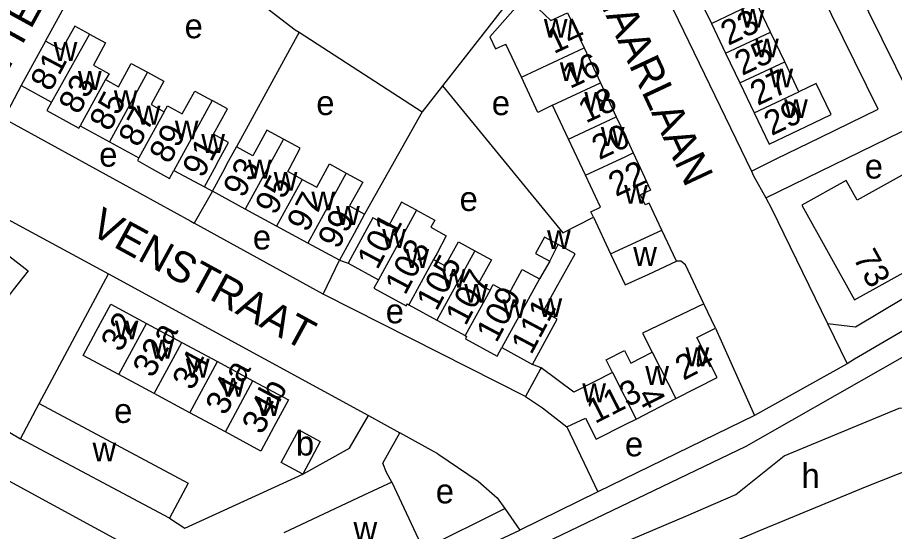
# Model space of a CAD drawing. Extents: x 158356 to 159894, y 383831 to 385260.
# Drawn here: x 159000.7 to 159143.9, y 383940.7 to 384024.6 of the extents above; entities that cross this region are included whole.
import ezdxf

# ---------------------------------------------------------------- set-up
doc = ezdxf.new("R2010")
doc.units = 0
for name, color, linetype in [('BLT_Basislijn', 7, 'Continuous'), ('BLT_Bebouwing', 7, 'Continuous'), ('BLT_Centroide', 7, 'Continuous'), ('BLT_Huisnummer', 7, 'Continuous'), ('BLT_Huisnummer_ tussenligend', 7, 'Continuous'), ('BLT_Huisnummer_reeks', 7, 'Continuous'), ('BLT_Onderverdeling_panden', 7, 'Continuous'), ('BLT_Straatnaam', 7, 'Continuous'), ('BLT_Vlakafsluiter', 7, 'Continuous')]:
    doc.layers.add(name, color=color, linetype=linetype)

msp = doc.modelspace()

# ---------------------------------------------------------------- linework, layer by layer
at = {"layer": 'BLT_Basislijn'}
for p, q in [((159005.27, 384020.8), (159012.56, 384034.13)), ((159080.04, 384026.23), (159070.07, 384013.46)), ((159046.67, 384022.22), (159036.45, 384003.53)), ((159046.67, 384022.22), (159066.78, 384009.26)), ((159122.87, 383995.19), (159165.67, 384016.08)), ((159070.07, 384013.46), (159066.78, 384009.26)), ((159066.78, 384009.26), (159057.34, 383992.51)), ((159124.58, 384001.54), (159124.64, 384001.55)), ((159032.51, 383996.29), (159029.52, 383991.08)), ((159050.62, 383979.47), (159029.52, 383991.08)), ((159050.62, 383979.47), (159053.25, 383985)), ((159053.25, 383985), (159054.67, 383984.53)), ((159015.54, 383982.8), (159058, 383959.64)), ((159132.98, 383974.65), (159136.17, 383968.1)), ((159114.69, 383973.88), (159121.02, 383959.64)), ((159086.19, 383967.45), (159084.77, 383967.99)), ((159058, 383959.64), (159063.12, 383956.82)), ((158997.04, 383958.25), (159001.16, 383955.84)), ((159090.38, 383957.81), (159095.47, 383947.17)), ((158999.29, 383949), (159026.07, 383934.41)), ((159025.49, 383942.85), (159028.01, 383941.24)), ((159045.95, 383923.82), (159082.7, 383940.91))]:
    msp.add_line(p, q, dxfattribs=at)
for points in [[(159130.07, 384059.7), (159124.27, 384056.8), (159146.23, 384012.21), (159163.28, 384020.54)], [(159131.86, 384005.09), (159141.23, 384009.67), (159118.45, 384056), (159109.62, 384051.58)], [(159054.11, 384048.78), (159044.27, 384037.62), (159041.24, 384026.76), (159041.56, 384026.03), (159046.04, 384022.62), (159046.67, 384022.22)], [(159102.32, 384048.1), (159098.34, 384046.21), (159098.18, 384045.79), (159100, 384041.97), (159120.53, 383999.56)], [(159001.28, 384013.52), (158998.47, 384008.16), (159028.98, 383991.37), (159029.52, 383991.08)], [(159070.07, 384013.46), (159089.76, 383989.46), (159094.72, 383992.05)], [(159120.53, 383999.56), (159124.58, 384001.54), (159131.86, 384005.09)], [(159120.53, 383999.56), (159120.9, 383998.78), (159122.87, 383995.19)], [(159132.98, 383974.65), (159137.54, 383974.11), (159175.88, 383997.05)], [(159122.87, 383995.19), (159123.83, 383993.43), (159132.98, 383974.65)], [(158964.85, 383970.22), (158990.55, 383992.57), (158992.72, 383993.66), (158996.3, 383993.18), (159015.54, 383982.8)], [(159178.17, 383992.69), (159137.39, 383968.84), (159136.17, 383968.1)], [(159183.57, 383991.39), (159156.91, 383975.82), (159119.63, 383954.56), (159067.69, 383929.66)], [(159112.79, 383977.86), (159109.76, 383984.24), (159108.99, 383984.83), (159108.28, 383984.85)], [(159004.24, 383961.61), (159015.54, 383982.8)], [(159083.67, 383962.76), (159050.83, 383979.35), (159050.62, 383979.47)], [(159088.93, 383926.66), (159102.6, 383932.65), (159121.62, 383940.74), (159139.46, 383948.12), (159156.35, 383954.78), (159168.72, 383959.06), (159184.17, 383964.54), (159200.11, 383969.53), (159206.72, 383971.51)], [(159081.85, 383931.35), (159109.84, 383943.2), (159117.99, 383946.75), (159125.88, 383953.07), (159144.67, 383960.83), (159152.29, 383961.04)], [(159047.27, 383950.08), (159054.9, 383954.29), (159058, 383959.64)], [(159121.02, 383959.64), (159095.47, 383947.17)], [(159061.79, 383948.76), (159060.92, 383950.34), (159060.34, 383951.85), (159063.12, 383956.82)], [(159069.32, 383953.39), (159063.12, 383956.82)], [(159069.32, 383953.39), (159075.91, 383948.92), (159079.03, 383946.2), (159080.25, 383944.43)], [(159028.01, 383941.24), (159047.27, 383950.08)], [(159066.93, 383937.81), (159080.25, 383944.43)], [(159080.25, 383944.43), (159082.7, 383940.91)]]:
    msp.add_lwpolyline(points, dxfattribs=at)
at = {"layer": 'BLT_Bebouwing'}
for p, q in [((159111.66, 384028.56), (159113.99, 384023.68)), ((159123.64, 384022.27), (159121.31, 384027.13)), ((159087.76, 384024.14), (159090.52, 384025.43)), ((159090.52, 384025.43), (159093.2, 384019.7)), ((159113.99, 384023.68), (159116.32, 384018.83)), ((159125.97, 384017.4), (159123.64, 384022.27)), ((159005.27, 384020.8), (159001.28, 384013.52)), ((159082.97, 384014.91), (159080.44, 384020.31)), ((159093.2, 384019.7), (159095.87, 384013.98)), ((159116.32, 384018.83), (159118.65, 384013.96)), ((159128.3, 384012.52), (159125.97, 384017.4)), ((159001.28, 384013.52), (159006.22, 384010.81)), ((159095.87, 384013.98), (159098.47, 384008.43)), ((159118.65, 384013.96), (159120.99, 384009.06)), ((159090.66, 384004.76), (159088.05, 384010.31)), ((159120.99, 384009.06), (159123.44, 384003.94)), ((159010.91, 384006.94), (159015.7, 384004.32)), ((159093.43, 383998.87), (159090.66, 384004.76)), ((159131.89, 384005.02), (159131.86, 384005.09)), ((159015.7, 384004.32), (159020.48, 384001.7)), ((159124.58, 384001.54), (159124.59, 384001.53)), ((159124.59, 384001.53), (159124.64, 384001.55)), ((159026.23, 383999.65), (159031.23, 383996.98)), ((159095.87, 383993.65), (159093.43, 383998.87)), ((159031.23, 383996.98), (159032.51, 383996.29)), ((159037.87, 383993.36), (159032.51, 383996.29)), ((159043, 383990.57), (159037.87, 383993.36)), ((159094.72, 383992.05), (159097.55, 383986.02)), ((159048.09, 383987.8), (159043, 383990.57)), ((159108.28, 383984.85), (159105.91, 383989.92)), ((159053.25, 383985), (159048.09, 383987.8)), ((159054.67, 383984.53), (159059.63, 383981.81)), ((159064.59, 383977.74), (159069.19, 383975.22)), ((159114.69, 383973.88), (159112.79, 383977.86)), ((159021.74, 383974.69), (159027.54, 383971.57)), ((159069.19, 383975.22), (159073.81, 383972.69)), ((159111.6, 383972.4), (159114.69, 383973.88)), ((159027.54, 383971.57), (159033.34, 383968.44)), ((159079.78, 383970.73), (159084.77, 383967.99)), ((159033.34, 383968.44), (159039.14, 383965.31)), ((159023.03, 383963.21), (159017.23, 383966.33)), ((159028.83, 383960.08), (159023.03, 383963.21)), ((159001.16, 383955.84), (159004.24, 383961.61)), ((159101.71, 383959.07), (159108.2, 383962.43)), ((159034.63, 383956.95), (159028.83, 383960.08)), ((159025.49, 383942.85), (159001.16, 383955.84)), ((159061.79, 383948.76), (159066.93, 383937.81))]:
    msp.add_line(p, q, dxfattribs=at)
for points in [[(159087.76, 384024.14), (159083.63, 384028.13), (159077.84, 384021.48), (159078.75, 384019.53), (159080.44, 384020.31)], [(159012.46, 384021.91), (159010.03, 384023.22), (159007.9, 384019.36), (159005.27, 384020.8)], [(159012.46, 384021.91), (159015.05, 384020.49), (159013.11, 384016.83), (159015.65, 384015.44), (159015.06, 384014.51)], [(159015.06, 384014.51), (159017.18, 384013.34), (159019.27, 384017.15), (159021.93, 384015.69)], [(159021.93, 384015.69), (159024.59, 384014.23), (159022.5, 384010.41), (159024.62, 384009.25)], [(159088.05, 384010.31), (159085.66, 384009.15), (159082.97, 384014.91)], [(159130.74, 384007.42), (159133.57, 384008.79), (159131.12, 384013.88), (159128.3, 384012.52)], [(159024.62, 384009.25), (159025.16, 384010.24), (159027.6, 384008.91), (159029.64, 384012.63), (159032.48, 384011.07)], [(159006.22, 384010.81), (159005.46, 384009.43), (159010.7, 384006.55), (159010.91, 384006.94)], [(159031.23, 383996.98), (159032.87, 384000), (159033.59, 384001.33), (159035.17, 384004.23), (159032.71, 384005.58), (159034.98, 384009.7), (159032.48, 384011.07)], [(159137.34, 383978.53), (159171.42, 383997.44), (159164.61, 384009.71), (159137.81, 383994.83), (159136.03, 383998.02), (159128.76, 383993.98), (159137.34, 383978.53)], [(159098.47, 384008.43), (159100, 384005.15), (159101.22, 384002.53)], [(159123.44, 384003.94), (159130.74, 384007.42)], [(159044.13, 384004.78), (159041.43, 384006.26), (159039.13, 384002.07), (159036.45, 384003.53)], [(159047.18, 383998.21), (159044.82, 383999.51), (159045.08, 384000), (159046.84, 384003.3), (159044.13, 384004.78)], [(159032.51, 383996.29), (159034.53, 384000), (159034.9, 384000.68), (159036.45, 384003.53)], [(159020.48, 384001.7), (159020.26, 384001.3), (159022.56, 384000), (159025.49, 383998.35), (159026.23, 383999.65)], [(159101.22, 384002.53), (159102.4, 384000), (159104.08, 383996.43), (159102.43, 383995.66)], [(159047.18, 383998.21), (159049.56, 383996.92), (159051.64, 384000.72), (159054.35, 383999.24)], [(159054.35, 383999.24), (159057.06, 383997.76), (159054.93, 383993.87), (159057.34, 383992.51)], [(159065.84, 383993.16), (159063.42, 383994.49), (159061.26, 383990.54), (159058.72, 383991.93), (159057.07, 383988.92), (159054.67, 383984.53)], [(159105.91, 383989.92), (159103.84, 383994.34), (159103.2, 383994.03), (159102.43, 383995.66)], [(159065.84, 383993.16), (159068.82, 383991.53), (159068.2, 383990.4), (159070.71, 383989), (159069.2, 383986.15), (159068.64, 383985.12)], [(159094.72, 383992.05), (159094.31, 383992.92), (159095.87, 383993.65)], [(159057.34, 383992.51), (159055.65, 383989.38), (159053.25, 383985)], [(158990.93, 383983.92), (158994.94, 383989.05), (159000, 383985.15), (159002.42, 383983.26), (159000, 383980.16), (158999.34, 383979.32), (158998.39, 383978.09)], [(159089, 383987.55), (159086.75, 383988.77), (159085.3, 383986.1), (159087.64, 383984.83)], [(159068.64, 383985.12), (159070.54, 383984.08), (159072.68, 383988), (159075.38, 383986.52)], [(159084.77, 383967.99), (159087.18, 383972.38), (159088.81, 383975.37), (159086.52, 383976.63), (159088.63, 383980.49), (159091.74, 383986.07), (159089, 383987.55)], [(159075.38, 383986.52), (159078.07, 383985.05), (159075.94, 383981.15), (159077.87, 383980.09)], [(159097.55, 383986.02), (159099.92, 383980.98), (159103.76, 383982.73), (159108.28, 383984.85)], [(159087.64, 383984.83), (159085.93, 383981.96)], [(159077.87, 383980.09), (159078.37, 383981.01), (159080.96, 383979.59), (159083.11, 383983.51), (159085.93, 383981.96)], [(159059.63, 383981.81), (159058.88, 383980.44), (159064.18, 383977.54), (159064.36, 383977.86), (159064.59, 383977.74)], [(159017.23, 383966.33), (159011.43, 383969.46), (159013.56, 383973.42), (159015.94, 383977.82), (159021.74, 383974.69)], [(159112.79, 383977.86), (159102.77, 383973.07), (159104.34, 383970)], [(159073.81, 383972.69), (159074.03, 383972.57), (159073.82, 383972.18), (159079.02, 383969.34), (159079.78, 383970.73)], [(159108.2, 383962.43), (159114.93, 383965.86), (159111.6, 383972.4)], [(159097.83, 383966.68), (159096.79, 383968.72), (159099.79, 383970.24), (159100.82, 383968.2), (159104.34, 383970)], [(159086.19, 383967.45), (159086.04, 383967.17), (159083.67, 383962.76)], [(159097.83, 383966.68), (159091.51, 383963.46), (159086.19, 383967.45)], [(159039.14, 383965.31), (159044.93, 383962.18), (159042.56, 383957.78), (159040.43, 383953.83), (159034.63, 383956.95)], [(159004.24, 383961.61), (159028.56, 383948.59), (159025.49, 383942.85)], [(159083.67, 383962.76), (159086.42, 383960.9), (159090.38, 383957.81)], [(159090.38, 383957.81), (159093.43, 383959.22), (159095.19, 383955.8), (159100, 383958.25), (159101.71, 383959.07)], [(159061.79, 383948.76), (159057.26, 383946.64), (159044.2, 383940.5)]]:
    msp.add_lwpolyline(points, dxfattribs=at)
msp.add_lwpolyline([(159047.27, 383950.08), (159043.75, 383951.98), (159046.62, 383957.29), (159050.13, 383955.39)], close=True, dxfattribs=at)
at = {"layer": 'BLT_Onderverdeling_panden'}
for p, q in [((159012.46, 384021.91), (159006.22, 384010.81)), ((159082.97, 384014.91), (159093.2, 384019.7)), ((159015.06, 384014.51), (159010.91, 384006.94)), ((159021.93, 384015.69), (159015.7, 384004.32)), ((159088.05, 384010.31), (159095.87, 384013.98)), ((159032.48, 384011.07), (159026.23, 383999.65)), ((159024.62, 384009.25), (159020.48, 384001.7)), ((159090.66, 384004.76), (159098.47, 384008.43)), ((159044.13, 384004.78), (159037.87, 383993.36)), ((159054.35, 383999.24), (159048.09, 383987.8)), ((159047.18, 383998.21), (159043, 383990.57)), ((159065.84, 383993.16), (159059.63, 383981.81)), ((159097.55, 383986.02), (159105.91, 383989.92)), ((159087.64, 383984.83), (159089, 383987.55)), ((159075.38, 383986.52), (159069.19, 383975.22)), ((159068.64, 383985.12), (159064.59, 383977.74)), ((159085.93, 383981.96), (159079.78, 383970.73)), ((159077.87, 383980.09), (159073.81, 383972.69)), ((159017.23, 383966.33), (159021.74, 383974.69)), ((159023.03, 383963.21), (159027.54, 383971.57)), ((159104.34, 383970), (159108.2, 383962.43)), ((159028.83, 383960.08), (159033.34, 383968.44)), ((159034.63, 383956.95), (159039.14, 383965.31))]:
    msp.add_line(p, q, dxfattribs=at)
for points in [[(159113.99, 384023.68), (159121.31, 384027.13)], [(159116.32, 384018.83), (159123.64, 384022.27)], [(159118.65, 384013.96), (159125.97, 384017.4)], [(159120.99, 384009.06), (159128.3, 384012.52)], [(159093.43, 383998.87), (159100, 384001.96), (159101.22, 384002.53)], [(159097.83, 383966.68), (159101.71, 383959.07)]]:
    msp.add_lwpolyline(points, dxfattribs=at)
at = {"layer": 'BLT_Vlakafsluiter'}
for p, q in [((159136.17, 383968.1), (159121.02, 383959.64)), ((159095.47, 383947.17), (159082.7, 383940.91))]:
    msp.add_line(p, q, dxfattribs=at)

# ---------------------------------------------------------------- texts
at = {"layer": 'BLT_Centroide'}
for s, p in [('w', (159118.81, 384022.97)), ('w', (159086.64, 384021.34)), ('e', (159027.98, 384021.25)), ('w', (159006.59, 384017.55)), ('w', (159121.14, 384018.12)), ('w', (159089.25, 384014.25)), ('w', (159010.56, 384012.81)), ('w', (159123.48, 384013.22)), ('w', (159016.42, 384009.69)), ('e', (159049.48, 384008.71)), ('e', (159078.14, 384008.69)), ('w', (159093.26, 384009.38)), ('w', (159020.16, 384007.16)), ('w', (159125.88, 384008.22)), ('w', (159026.38, 384004.73)), ('w', (159095.95, 384003.66)), ('w', (159030.7, 384002.53)), ('e', (159014.03, 384000.28)), ('w', (159038.31, 383998.34)), ('e', (159139.04, 383998.34)), ('w', (159042.53, 383996.34)), ('w', (159099.75, 383994.23)), ('w', (159048.67, 383993.14)), ('e', (159072.88, 383993.04)), ('w', (159052.72, 383990.77)), ('w', (159060.25, 383987.02)), ('e', (159039.12, 383986.76)), ('w', (159087.16, 383986.83)), ('w', (159064.03, 383983.75)), ('w', (159101.24, 383984.07)), ('w', (159069.98, 383980.52)), ('w', (159073.64, 383978.06)), ('w', (159079.88, 383975.55)), ('w', (159085.77, 383975.72)), ('e', (159060.82, 383974.7)), ('w', (159016.58, 383972.08)), ('w', (159022.38, 383968.95)), ('w', (159109.77, 383967.69)), ('w', (159028.19, 383965.83)), ('w', (159103.2, 383964.64)), ('w', (159033.98, 383962.7)), ('w', (159092.92, 383961.81)), ('e', (159016.47, 383958.43)), ('w', (159039.78, 383959.58)), ('b', (159046.16, 383953.11)), ('e', (159099.89, 383952.98)), ('w', (159012.94, 383952.16)), ('h', (159128.71, 383947.83)), ('e', (159068.99, 383945.29)), ('w', (159055.56, 383939.16))]:
    msp.add_text(s, height=4, dxfattribs=at).set_placement(p)
at = {"layer": 'BLT_Huisnummer'}
for s, rotation, p in [('14', 25.1687, (159088.26, 384018.63)), ('25', 25.4917, (159119.02, 384015.08)), ('81', 62.0608, (159006.1, 384012.38)), ('18', 25.1687, (159093.49, 384007.3)), ('85', 62.0608, (159015.73, 384005.86)), ('29', 25.4917, (159123.82, 384005.26)), ('91', 62.0608, (159030.93, 383998.27)), ('93', 62.0608, (159037.57, 383995.01)), ('22', 25.1687, (159098.39, 383995.31)), ('99', 62.0608, (159053.03, 383986.64)), ('101', 62.0608, (159059.45, 383983.3)), ('105', 62.0608, (159069.12, 383976.55)), ('111', 62.0608, (159084.59, 383969.43)), ('32', 61.6698, (159017.58, 383969.83)), ('34', 61.667, (159029.25, 383963.57)), ('24', 26.9932, (159109.42, 383965.31)), ('34b', 61.6682, (159040.61, 383956.36)), ('113', 26.9986, (159094.98, 383958.23)), ('4', 296.9982, (159101.8, 383962.99))]:
    msp.add_text(s, height=4, rotation=rotation, dxfattribs=at).set_placement(p)
at = {"layer": 'BLT_Huisnummer_ tussenligend'}
for s, rotation, p in [('23', 25.4917, (159116.75, 384019.99)), ('16', 25.1687, (159090.9, 384012.94)), ('27', 25.4917, (159121.55, 384010.17)), ('83', 62.0608, (159010.7, 384008.64)), ('87', 62.0608, (159020.47, 384003.27)), ('89', 62.0608, (159025.5, 384000.56)), ('20', 25.1687, (159095.68, 384001.32)), ('95', 62.0608, (159042.79, 383992.2)), ('97', 62.0608, (159047.98, 383989.39)), ('103', 62.0608, (159063.99, 383979.15)), ('107', 62.0608, (159073.86, 383974.13)), ('109', 62.0608, (159078.9, 383971.38)), ('32a', 61.6698, (159022.78, 383965.62)), ('34a', 61.6682, (159034.66, 383959.49))]:
    msp.add_text(s, height=4, rotation=rotation, dxfattribs=at).set_placement(p)
at = {"layer": 'BLT_Huisnummer_reeks'}
msp.add_text('73', height=4, rotation=299.036, dxfattribs=at).set_placement((159137.05, 383985.39))
at = {"layer": 'BLT_Straatnaam'}
for s, rotation, p in [('1E TERBORGSTRAAT', 61.2486, (158996.06, 384010.21)), ('ZEVENAARLAAN', 295.0902, (159087.24, 384045.18)), ('VENSTRAAT', 331.3703, (159012.26, 383989.41))]:
    msp.add_text(s, height=5, rotation=rotation, dxfattribs=at).set_placement(p)

doc.saveas('drawing.dxf')
